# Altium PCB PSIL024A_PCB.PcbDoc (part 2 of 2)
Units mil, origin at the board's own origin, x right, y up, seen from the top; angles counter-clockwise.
Board outline 5700 x 3550 mil, 4 copper layers (Top Layer, MidLayer1, MidLayer2, Bottom Layer), stack 61.2 mil thick; 205 components, 107 nets, 481 pads, 240 vias.
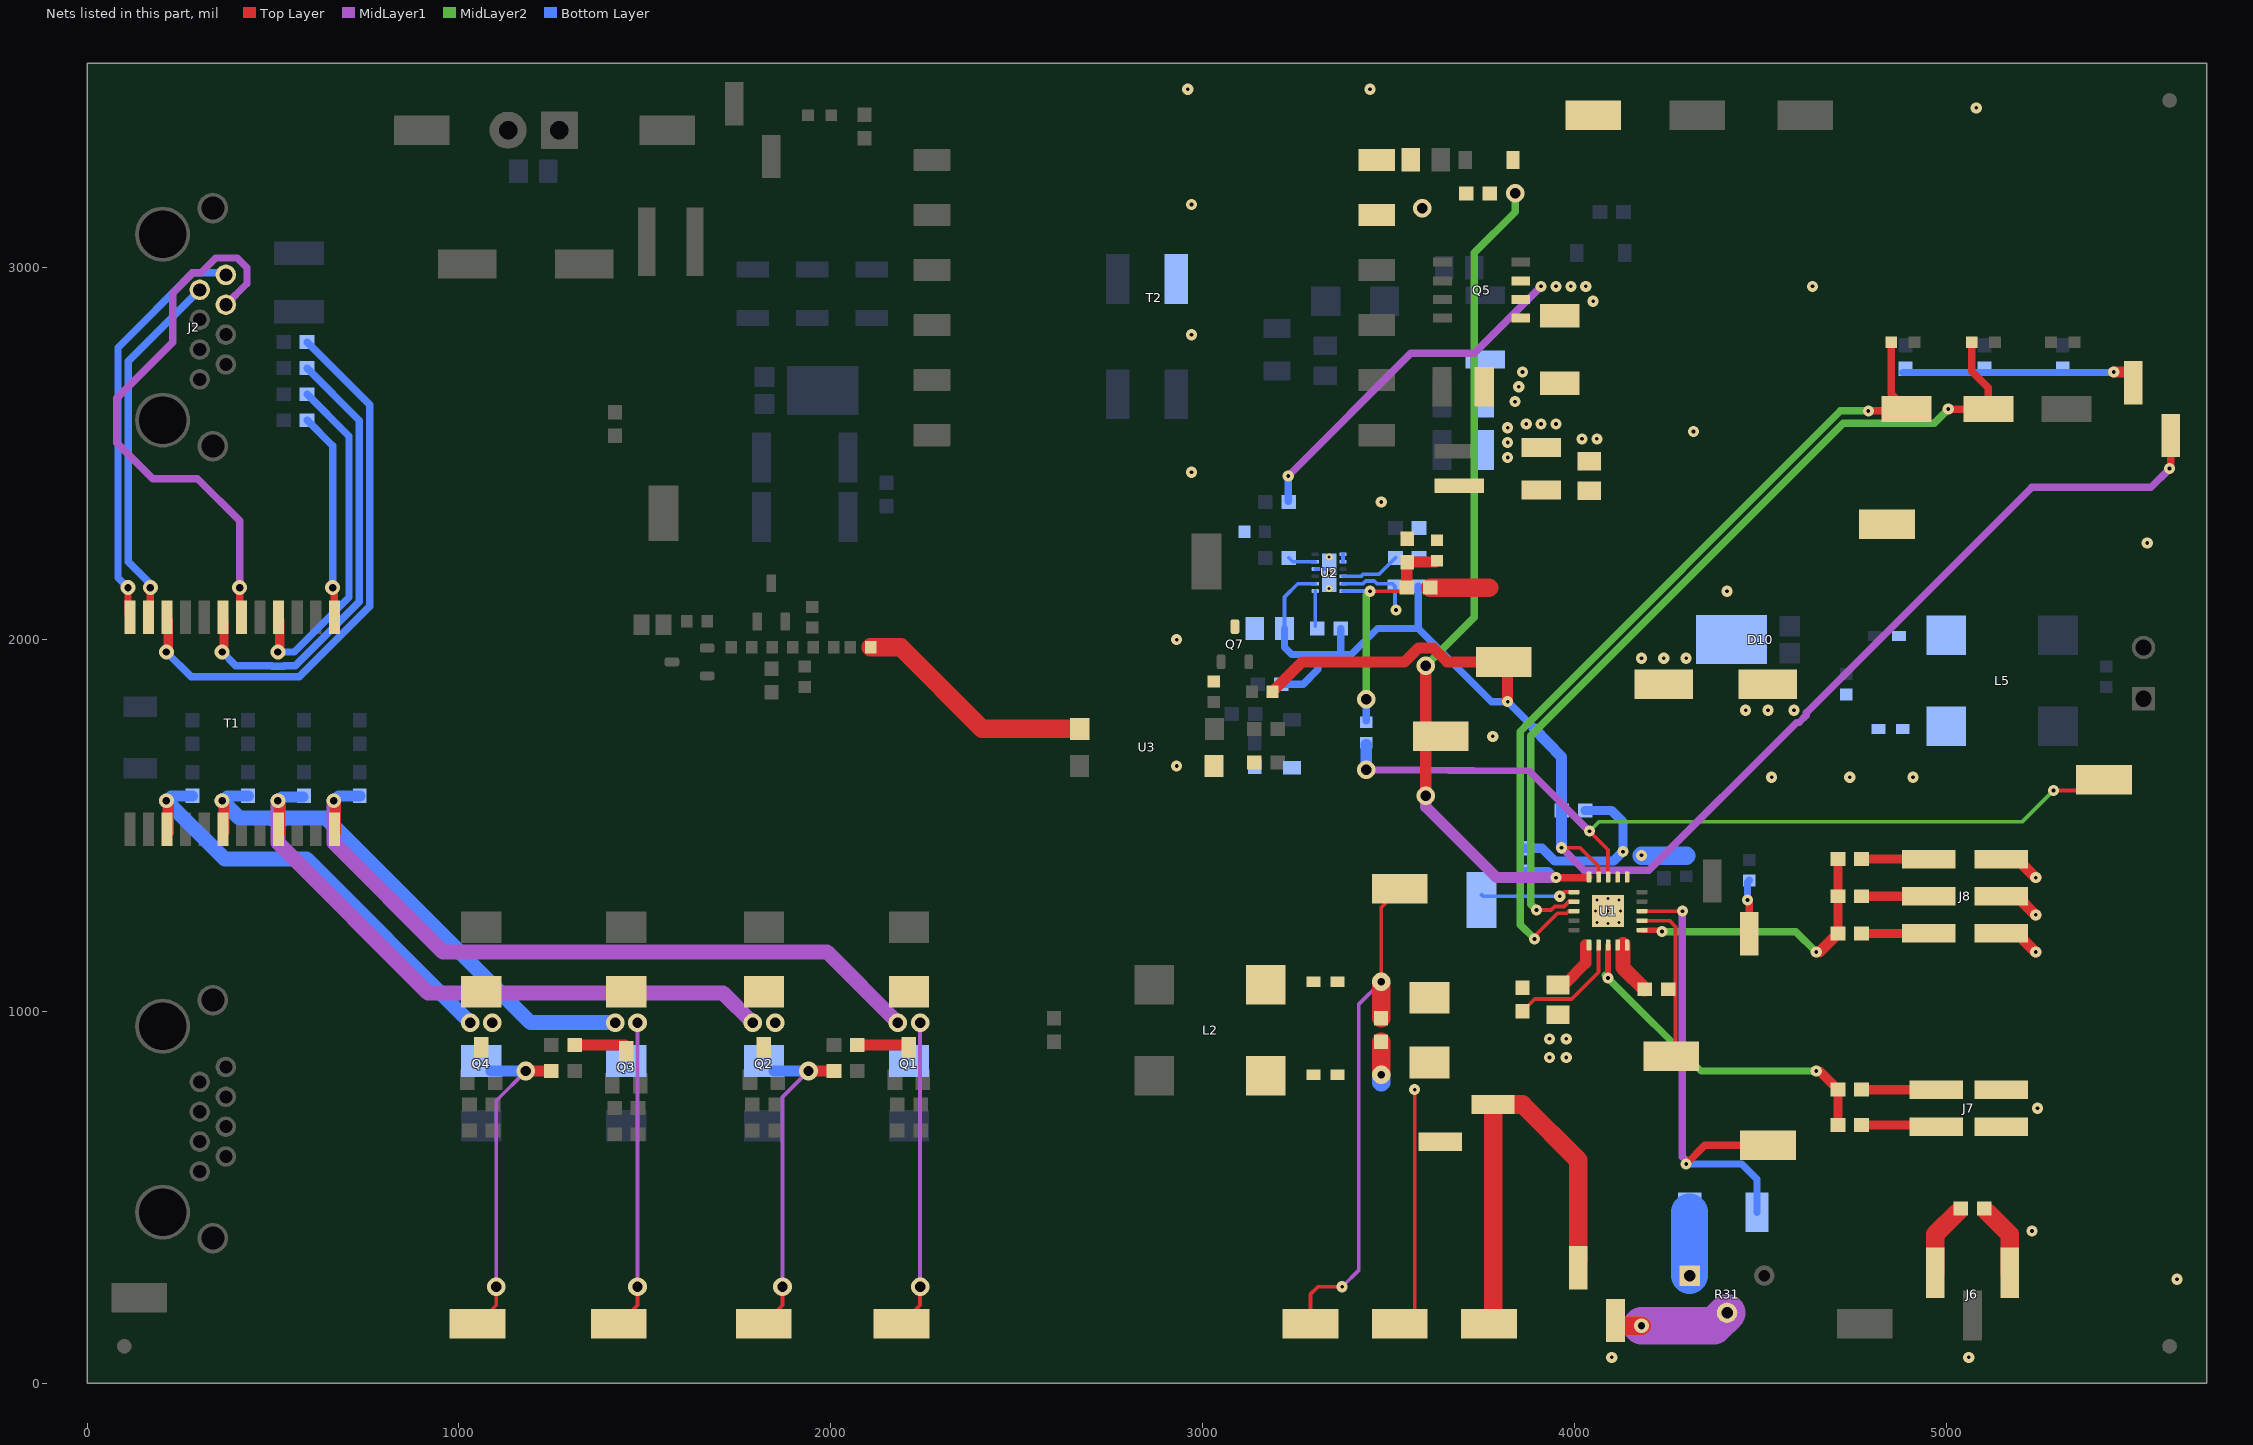
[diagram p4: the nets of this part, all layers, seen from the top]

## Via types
v1: diameter 30, hole 10, Top Layer to Bottom Layer, 128 vias
v2: diameter 50, hole 28, Top Layer to Bottom Layer, 77 vias
v3: diameter 40, hole 20, Top Layer to Bottom Layer, 21 vias
v4: diameter 19.68, hole 7.87, Top Layer to Bottom Layer, 8 vias
v5: diameter 20, hole 8, Top Layer to Bottom Layer, 4 vias
v6: diameter 50, hole 20, Top Layer to Bottom Layer, 2 vias

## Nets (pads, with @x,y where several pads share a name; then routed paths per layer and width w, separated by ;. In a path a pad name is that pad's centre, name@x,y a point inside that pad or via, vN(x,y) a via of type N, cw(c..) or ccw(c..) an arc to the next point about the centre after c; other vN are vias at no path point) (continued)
NetJ2_6: J2.6 T1.6 | length 1509.2
  Top Layer w20: T1.6@410,2065.04 v3(410,2140)
  MidLayer1 w20: J2.6@372.99,2900.63 430,2957.64 430,3000 403.62,3026.38 346.38,3026.38 306.22,2986.22 284.09,2986.22 230,2932.13 230,2799.42 80,2649.42 80,2530 176.77,2433.23 296.77,2433.23 410,2320 v3(410,2140)
NetJ2_7: J2.7 T1.11 | length 979.6
  Top Layer w20: T1.11@170,2065.04 v3(170,2140)
  Bottom Layer w20: v3(170,2140) 170,2150 111.04,2208.96 111.04,2748.91 J2.7@302.91,2940.79
NetJ2_8: J2.8 T1.12 | length 1109.7
  Top Layer w20: T1.12@110,2065.04 v3(110,2140)
  Bottom Layer w20: v3(110,2140) 83.17,2166.83 83.17,2785.29 284.09,2986.22 372.99,2986.22 J2.8@372.99,2980.94
NetJ4_1: J4.1 R17.1 | length 140.4
  Top Layer w20: J4.1@4470,1209.13 v1@4470,1295
  Bottom Layer w20: v1(4465,1300) 4465,1347.44 R17.1@4470,1352.44
NetJ5_2: J5.2 R20.2 R21.2 R22.2 | length 623.7
  Top Layer w30: v1(5450,2720) J5.2@5510,2720
  Bottom Layer w20: R20.2@4882.8,2718.49 5312.8,2718.49 v1@5446.51,2718.49
NetJ6_1: J6.1 R19.1 | length 187.8
  Top Layer w50: J6.1@4970,297.5 4970,401.5 R19.1@5030,460
NetJ7_2: J7.2 R24.1 | length 203.1
  Top Layer w25: R24.1@4771.5,695 4967.5,695 J7.2@4972.5,690
NetJ7_4: J7.4 R25.1 | length 201
  Top Layer w25: R25.1@4771.5,790 J7.4@4972.5,790
NetJ8_2: J8.2 R27.1 | length 178.5
  Top Layer w25: R27.1@4771.5,1210 J8.2@4950,1210
NetJ8_4: J8.4 R28.1 | length 181.1
  Top Layer w25: R28.1@4771.5,1310 J8.4@4952.56,1310
NetJ8_6: J8.6 R29.1 | length 178.5
  Top Layer w25: R29.1@4771.5,1410 J8.6@4950,1410
NetJ10_2: J10.2 R31.2 | length 300.4
  Top Layer w50: J10.2@4124.13,155 v3(4180,155)
  MidLayer1 w100: v3(4180,155) 4375,155 R31.2@4410,190
NetL1_1: L1.1 L2.1
NetL2_4: L2.4 L3.1
NetL4_1: L4.1 L5.1
NetL5_4: L5.4 L6.1
NetQ5_1: Q5.1 Q5.2 Q5.3 R38.2 R42.2 | length 959.8
  MidLayer1 w20: v1(3230,2440) 3560,2770 3730,2770 v1(3910,2950)
  Bottom Layer w20: R42.2@3230,2371.5 v1(3230,2440)
  other v1: 4050,2910 3950,2950 3990,2950 4030,2950
NetR5_1: R5.1 T1.10 | length 1520.1
  Top Layer w25: v3(213.15,1966.85) 218.15,1971.85 T1.10@218.15,2051.89
  Bottom Layer w20: v3(213.15,1966.85) 280,1900 570,1900 760,2090 760,2631.5 R5.1@591.5,2800
NetR6_1: R6.1 T1.7 | length 1229.6
  Top Layer w25: v3(363.15,1966.85) 368.15,1971.85 T1.7@368.15,2051.89
  Bottom Layer w20: v3(363.15,1966.85) 400,1930 496.44,1930 497.46,1928.98 528.84,1928.98 529.86,1930 560,1930 732.13,2102.13 732.13,2589.37 R6.1@591.5,2730
NetR7_1: R7.1 T1.4 | length 932.1
  Top Layer w25: v3(513.15,1966.85) 518.15,1971.85 T1.4@518.15,2051.89
  Bottom Layer w20: v3(513.15,1966.85) 557.43,1966.85 704.25,2113.67 704.25,2547.24 R7.1@591.5,2660
NetR8_1: R8.1 T1.1 | length 570.4
  Top Layer w10: v3(660,2140) v3@665,2135
  Top Layer w20: T1.1@665,2060.04 v3@665,2135
  Bottom Layer w20: R8.1@591.5,2590 660,2521.5 v3(660,2140) v3@660,2130
NetR23_1: R23.1 U1.2 | length 320.4
  Top Layer w10: R23.1@3860.25,1001 3892.62,1033.38 3992.33,1033.38 4064.41,1105.45 U1.2@4064.41,1178.46
NetR24_2: R24.2 R25.2 U1.3 | length 936.8
  Top Layer w15: v1(4090,1090) U1.3@4090,1178.46
  Top Layer w25: v1(4650,840) 4658.5,840 R25.2@4708.5,790 R24.2@4708.5,695
  MidLayer2 w20: v1@4082.5,1097.5 v1(4090,1090) 4340,840 v1(4650,840)
NetR26_1: R26.1 TP9.1 U1.13 | length 2315.6
  Top Layer w10: v1@4045,1485 v1(4040,1485) 4090,1435 U1.13@4090,1361.54 ; v1(5288,1594.5) 5395.25,1594.5 TP9.1@5423.75,1623
  MidLayer1 w20: v2(3440,1650) 3878.25,1646.75 v1(4040,1485)
  MidLayer2 w10: v1(4040,1485) 4065,1510 5203.5,1510 v1(5288,1594.5)
  Bottom Layer w30: v2@3440,1660 R26.1@3440,1718.5
NetR27_2: R27.2 R28.2 R29.2 U1.6 | length 766.6
  Top Layer w10: v1@4235,1210 v1(4235,1215) ; v1(4650,1160) v1@4658.5,1160
  Top Layer w15: U1.6@4181.54,1218.82 v1@4226.18,1218.82
  Top Layer w25: R27.2@4708.5,1210 R28.2@4708.5,1310 R29.2@4708.5,1410
  Top Layer w30: v1@4658.5,1160 R27.2@4708.5,1210
  MidLayer2 w20: v1(4235,1215) 4595,1215 v1(4650,1160)
NetR30_1: R30.1 R31.1 | length 169.4
  Bottom Layer w100: R31.1@4309.45,290.55 R30.1@4309.45,460
NetR30_2: R30.2 TP14.1 U1.8 | length 1327.2
  Top Layer w10: U1.8@4181.54,1270 v1(4290,1270)
  Top Layer w20: v1(4300,590) 4350,640 TP14.1@4520,640
  MidLayer1 w20: v1(4290,1270) 4290,610 v1@4305,595
  Bottom Layer w20: v1(4300,590) 4450,590 4490.55,549.45 R30.2@4490.55,460
NetR32_1: R32.1 TP17.1 U1.7 | length 433.2
  Top Layer w10: U1.7@4181.54,1244.41 4255,1244.41 4271.5,1227.92 4271.5,1070 TP17.1@4271.5,891.5
NetR39_2: R39.2 T2.6
NetR40_2: pad.11 R40.2 U2.11 | length 213.5
  Bottom Layer w10: U2.11@3377.4,2150.47 3431.05,2150.47 3438.45,2157.87 3461.55,2157.87 3468.95,2150.47 3510.2,2150.47 R40.2@3516.97,2143.7 3516.97,2083.03 v1(3520,2080)
NetR41_1: R41.1 U2.5 | length 75.4
  Bottom Layer w10: R41.1@3231.5,2220 3241.97,2209.53 U2.5@3302.6,2209.53
NetR43_2: pad.10 R43.2 U2.10 | length 161.7
  Bottom Layer w10: U2.10@3377.4,2170.16 3425.46,2170.16 3431.05,2175.75 3474.25,2175.75 R43.2@3518.5,2220
NetR54_1: R54.1 U3.1 | length 652.3
  Top Layer w50: R54.1@2107.56,1980 2187.56,1980 2407.56,1760 ; 2408.17,1760 U3.1@2669.39,1760
NetR63_2: R63.2 U2.1 | length 94.9
  Bottom Layer w10: R63.2@3302.6,2035.91 U2.1@3302.6,2130.79
NetTP16_1: TP16.1 U1.16 | length 255.2
  Top Layer w10: v1(3960,1310) 3971.18,1321.18 U1.16@3998.46,1321.18
  Bottom Layer w10: TP16.1@3749.74,1314.36 3754.1,1310 v1(3960,1310)
PR12: C1.1 D1.2 D6.1 Q1.3 R10.2 T1.24 TP1.1 | length 2935.1
  Top Layer w10: TP1.1@2190,160 2240,210 v2(2240,260)
  Top Layer w30: T1.24@668.15,1481.81 v3@668.15,1561.85 ; R10.2@2071.5,910 2190,910
  MidLayer1 w10: v2(2240,260) v2(2240,970)
  MidLayer1 w40: v3(663.15,1566.85) 663.15,1453.7 956.85,1160 1990,1160 v2(2180,970)
  Bottom Layer w30: v3(663.15,1566.85) 676.3,1580 C1.1@733.15,1580
PR36: C2.1 D2.2 D7.1 Q2.3 R9.2 T1.21 TP2.1 | length 2632.6
  Top Layer w10: TP2.1@1820,160 1870,210 v2(1870,260)
  Top Layer w30: T1.21@518.15,1481.81 v3@518.15,1561.85 ; v2(1940,840) R9.2@2008.5,840
  MidLayer1 w10: v2(1870,260) 1870,770 v2(1940,840)
  MidLayer1 w40: v3(513.15,1566.85) 513.15,1453.7 916.85,1050 1710,1050 v2(1790,970)
  Bottom Layer w30: v3(513.15,1566.85) 523.15,1576.85 C2.1@580,1576.85 ; D7.1@1847.01,840 v2(1940,840)
  other v2: 1850,970
PR45: C3.1 D3.2 D8.1 Q3.3 R12.2 T1.18 TP3.1 | length 2434.6
  Top Layer w10: TP3.1@1430,160 1480,210 v2(1480,260)
  Top Layer w30: T1.18@368.15,1481.81 v3@368.15,1561.85 ; R12.2@1311.5,910 Q3.3@1446.69,910
  MidLayer1 w10: v2(1480,970) 1480,280 v2@1500,260
  Bottom Layer w30: v3(363.15,1566.85) 376.3,1580 C3.1@433.15,1580
  Bottom Layer w40: v3(363.15,1566.85) 410,1520 492.3,1520 493.32,1518.98 532.98,1518.98 534,1520 642.3,1520 1192.3,970 v2(1420,970)
PR78: C4.1 D4.2 D9.1 Q4.3 R11.2 T1.15 TP4.1 | length 2114.9
  Top Layer w10: TP4.1@1050,160 1100,210 v2(1100,260)
  Top Layer w30: T1.15@218.15,1481.81 v3@218.15,1561.85 ; v2(1180,840) R11.2@1248.5,840
  MidLayer1 w10: v2(1100,260) 1100,760 v2(1180,840)
  Bottom Layer w30: v3(213.15,1566.85) 226.3,1580 C4.1@283.15,1580 ; D9.1@1087.01,840 v2(1180,840)
  Bottom Layer w40: v3(213.15,1566.85) 370,1410 590,1410 v2(1030,970)
  other v2: 1090,970
RTN: C13.2 C15.1 C16.2 C17.2 C18.2 C21.1 C22.2 C23.2 C24.2 C25.2 C33.2 C34.2 C35.2 C36.2 C38.2 C39.2 C40.2 C41.2 C43.2 D19.2 L6.2 pad.4 pad.7 pad.8 Q7.3 R18.1 R36.1 R37.1 R38.1 R43.1 T2.5 TP10.1 TP23.1 U1.11 U1.12 U2.4 U2.7 U2.8 U2.13@3340,2180 U3.3 | length 647.3
  Bottom Layer w10: U2.4@3302.6,2189.84 U2.13@3330.16,2189.84 ; U2.8@3377.4,2209.53 U2.7@3377.4,2229.21
  Bottom Layer w25: C16.2@3868.25,1439.25 3912.24,1439.25 3946.61,1404.88 4104.63,1404.88 v1@4130,1430.25 ; C18.2@4028.25,1540.5 4099.25,1540.5 4130,1509.75 v1@4130,1430.25 ; v1@4130.75,1430.25 v1@4130,1430.25
  Bottom Layer w50: v1@4181.14,1418.86 C15.1@4300,1418.86
  other v1: 4180,1420 4130,1430 4530,1630 4740,1630 4910,1630 2930,1660 3780,1740 4460,1810 4520,1810 4590,1810 2930,2000 4410,2130 5540,2260 3480,2370 2970,2450 3820,2490 3820,2530 4020,2540 4060,2540 4320,2560 3820,2570 3870,2580 3910,2580 3950,2580 3840,2640 3850,2680 3860,2720 2970,2820 4640,2950 2970,3170 5080,3430 2960,3480 3450,3480
  other v2: 3590,3160
  other v4: 3340,2137.68 3340,2180 3340,2222.32
TPH: D11.1 TP11.1 U1.18 | length 2310.9
  Top Layer w10: v1(3892.5,1195) 3892.5,1202.5 3954.25,1264.25 3978.95,1264.25 3984.7,1270 U1.18@3998.46,1270
  Top Layer w20: v1(4790,2615) 4887.82,2615 TP11.1@4892.8,2619.98 4851.3,2661.48 D11.1@4851.3,2799.98
  MidLayer2 w20: v1(3892.5,1195) 3854.25,1233.25 3854.25,1753.09 3860,1758.84 3860,1759.42 3870,1769.42 3870,1770 4715,2615 v1(4790,2615)
TPL: D12.1 TP12.1 U1.17 | length 2380
  Top Layer w10: v1(3897.75,1272.75) 3936.57,1272.75 3947.2,1283.38 3948.45,1282.13 3971.55,1282.13 3985.01,1295.59 U1.17@3998.46,1295.59
  Top Layer w20: v1(5005,2620) TP12.1@5112.8,2619.98 5112.8,2677.2 5067.86,2722.14 D12.1@5067.86,2799.98
  MidLayer2 w20: v1(3897.75,1272.75) 3882.13,1288.37 3882.13,1741.55 3890,1749.42 3890,1750 4722.13,2582.13 4967.13,2582.13 v1(5005,2620)
UVLO: C33.1 pad.12 R26.2 R34.1 R37.2 U2.12 | length 663.4
  Top Layer w10: v1(3450,2130) R34.1@3560,2130
  Top Layer w30: R34.1@3548.5,2140 R37.2@3548.5,2207.01 ; R37.2@3550,2208.5 C33.1@3626.06,2208.5
  MidLayer2 w20: v2(3440,1840) v1@3440,2120
  Bottom Layer w10: U2.12@3377.4,2130.79 v1@3449.21,2130.79
  Bottom Layer w20: R26.2@3440,1781.5 v2(3440,1840)
VCIN: C16.1 C39.1 D17.1 TP25.1 U1.15 | length 2355.7
  Top Layer w20: v1(3950,1360) 4037.28,1360 U1.15@4038.82,1361.54
  Top Layer w30: v2(3600,1580) v2(3600,1930)
  MidLayer1 w30: v2(3600,1580) 3600,1550 3790,1360 v1(3950,1360)
  MidLayer2 w20: v2(3600,1930) 3730,2060 3730,3040 3840,3150 v2(3840,3200)
  Bottom Layer w25: C16.1@3868.75,1376.5 3928.5,1376.5 3945,1360 v1(3950,1360)
VCOUT: C18.1 C40.1 J5.1 pad.2 R40.1 R45.2 R62.2 R63.1 TP26.1 U1.14 U2.2 | length 4881.1
  Top Layer w10: v1(3965,1440.25) 4014.75,1440.25 4064.41,1390.59 U1.14@4064.41,1361.54
  Top Layer w20: v1@5602.8,2462.2 J5.1@5602.8,2549.13
  Top Layer w30: R62.2@3187.56,1860 3267.56,1940 3542.3,1940 3580.17,1977.87 3619.83,1977.87 3657.7,1940 TP26.1@3810,1940 ; v1(3820,1833.26) TP26.1@3820,1940
  MidLayer1 w20: v1(3965,1440.25) 4025.25,1380 4200,1380 4597.13,1777.13 4603.62,1777.13 4622.87,1796.38 4622.87,1802.87 5230,2410 5550,2410 v1(5600,2460)
  Bottom Layer w10: C40.1@3220,2030 3220,2114.61 3255.86,2150.47 U2.2@3302.6,2150.47
  Bottom Layer w20: R45.2@3211.5,1880 3270,1880 3310,1920 3310,1960 ; C40.1@3220,2030 3220,1980 3240,1960 3310,1960 ; 3371.5,1961.5 R63.1@3371.5,2030 ; R40.1@3579.96,2143.7 3579.96,2030.04 ; v1(3820,1833.26) 3776.74,1833.26 3579.96,2030.04 ; v1(3820,1833.26) 3891.65,1761.65 ; 3310,1960 3400,1960 3470.04,2030.04 3579.96,2030.04
  Bottom Layer w30: 3890.83,1760.84 3965.25,1684.75 3965.1,1540.5 v1(3965,1440.25)
VDD: C8.1 C17.1 C19.1 C21.2 C22.1 D5.1 D10.3 L1.2 L7.1 R23.2 R34.2 TP7.1 TP8.1 U1.1 | length 1721.3
  Top Layer w10: TP7.1@3290,160 3290,240 3310,260 v1(3375,260) ; v6@3480,1072.44 v6(3480,1080) 3480,1280 TP8.1@3530,1330 ; C19.1@3955.5,1071.25 C19.1@3981.25,1071.25
  Top Layer w30: C19.1@3972.43,1072.43 4030,1130 4030,1179.65
  Top Layer w50: C8.1@3480,981.5 v6@3480,1072.44 ; R34.2@3611.5,2140 3770,2140
  MidLayer1 w10: v1(3375,260) 3420,305 3420,1020 v6(3480,1080)
  other v1: 4180,1950 4240,1950 4300,1950
VSS: C19.2 J6.3 J7.1 J7.3 J8.1 J8.3 J8.5 J9.1 J10.1 R19.2 R32.2 TP18.1 U1.4 U1.5 U1.21@4090,1270 | length 1697.8
  Top Layer w10: J10.1@4000,320.87 J10.1@4010,330.87
  Top Layer w30: J8.1@5190,1210 v1(5240,1160) ; J8.3@5190,1310 v1(5240,1260) ; J8.5@5190,1410 v1(5240,1360)
  Top Layer w40: 4130,1180 4130,1118.5 R32.2@4188.5,1060
  Top Layer w50: TP18.1@3780.87,170.87 J9.1@3780.87,750 3860,750 4010,600 J10.1@4010,330.87 ; R19.2@5110,460 5170,401.5 J6.3@5170,297.5
  other v1: 4100,70 5060,70 5620,280 5230,410 5245,740 3932.5,876.5 3977.5,876.5 3932.5,926.5 3977.5,926.5
  other v4: 4090,1236.54 4056.54,1270 4090,1270 4123.46,1270 4090,1303.46
  other v5: 4060,1240 4120,1240 4060,1300 4120,1300
VSS1: C8.2 D5.2 J9.2 L3.2 TP15.1 | length 755.1
  Top Layer w10: TP15.1@3530,160 3570,200 v1(3570,790)
  Top Layer w50: v6(3480,830) C8.2@3480,918.5
  Bottom Layer w50: v6@3480,810 v6(3480,830)
pads on no net: FID1.1 FID2.1 FID3.1 FID4.1 FID5.1 FID6.1 H1.0 H2.0 H3.0 H4.0 R31.3 SH-J1.0 SH-J2.0 SH-J3.0 SH-J4.0 SH-J5.0 SH-J6.0 SH-J7.0 SH-J8.0 T2.7 T2.10 U1.20 U1.21@4066.77,1246.77 U1.21@4066.77,1293.23 U1.21@4113.23,1246.77 U1.21@4113.23,1293.23 U2.13@3340,2153.03 U2.13@3340,2206.97
copper on no net:
  other v1: 2380,840

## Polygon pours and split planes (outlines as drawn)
VDD on Top Layer "TOP_LAYER_VDD_P106" (solid, remove dead copper, pour order 106): 3620,2430 3620,2340 3770,2340 3770,2430
GND on Top Layer "TOP_LAYER_GND_P088" (solid, remove dead copper, pour order 88): 2800,1580 890,1580 890,3090 890,3510 2800,3510
EARTH on Top Layer "TOP_LAYER_EARTH_P028" (solid, remove dead copper, pour order 28): 40,1480 2550,1480 2550,40 40,40
EARTH on Top Layer "TOP_LAYER_EARTH_P020" (solid, remove dead copper, pour order 20): 793.74,3240 786.81,70 40,70 40,3240
VSS on Top Layer "TOP_LAYER_VSS_P014" (solid, remove dead copper, pour order 14): 4050,1310 4130,1310 4510,1310 4605,1310 4765,1470 5660,1470 5660,40 4050,40
RTN on Top Layer "TOP_LAYER_RTN_P010" (solid, remove dead copper, pour order 10): 4110,1345 4146.91,1345 4421.91,1580 4730,1580 4735,2990 4420,2990 4420,1890 4420,1845 4110,1581.04
VDD on Top Layer "TOP_LAYER_VDD_P008" (solid, remove dead copper, pour order 8): 3340,1045 3698.58,1045 3698.58,1048.58 3910,1048.58 3890,1330 3890,1410 4322.25,1705.09 4318.74,2430 3955,2430 3955,1790 3690,1540 3548.57,1405.71 3340,1405.71
VSS on Top Layer "TOP_LAYER_VSS_P006" (solid, remove dead copper, pour order 6): 3740,1020 3740,725 4150,725 4150,1000 4150,1200 4135,1200 4125,1200 4120,1200 4115,1200 4115,1105 4030,1020 4025,1025 3740,1025
VSS1 on Top Layer "TOP_LAYER_VSS1_P004" (solid, remove dead copper, pour order 4): 3450,620 3685,620 3685,1010 3690,1015 3450,1015
NetC7_1 on Top Layer "TOP_LAYER_NETC7_1_P002" (solid, remove dead copper, pour order 2): 2630,960 2520,960 2520,1110 2630,1110
NetC7_2 on Top Layer "TOP_LAYER_NETC7_2_P000" (solid, remove dead copper, pour order 0): 2640,785 2525,785 2525,940 2640,940
RTN on Top Layer "TOP_LAYER_RTN_P064" (solid, remove dead copper, pour order 64): 3345,1870 3345,1578.98 3590,1578.98 3590,1860 3585,1865 3580,1870
RTN on Top Layer "TOP_LAYER_RTN_P080" (solid, remove dead copper, pour order 80): 5637.68,2230 4867.68,2230 4867.68,3510 5637.68,3510
VDD on Top Layer "TOP_LAYER_VDD_P114" (solid, remove dead copper, pour order 114): 3640.35,2430 3640.35,2110 3970.35,2110 3970.35,2430 3640.35,2430
RTN on Top Layer "TOP_LAYER_RTN_P116" (solid, remove dead copper, pour order 116): 5670,1580 2900,1580 2900,3510 5670,3510
EARTH on Bottom Layer "BOTTOM_LAYER_EARTH_P034" (solid, remove dead copper, pour order 34): 40,3240 790,3240 790,1480 40,1480
EARTH on Bottom Layer "BOTTOM_LAYER_EARTH_P026" (solid, remove dead copper, pour order 26): 2550,1480 2550,40 40,40 40,1480
VSS on Bottom Layer "BOTTOM_LAYER_VSS_P012" (solid, remove dead copper, pour order 12): 4050,1310 4130,1310 4510,1310 4605,1310 4765,1470 5660,1470 5660,40 5530,40 4050,40
RTN on Bottom Layer "BOTTOM_LAYER_RTN_P054" (solid, remove dead copper, pour order 54): 5120,1584.51 2900,1584.51 2900,3510 5120,3510
GND on Bottom Layer "BOTTOM_LAYER_GND_P062" (solid, remove dead copper, pour order 62): 2800,1580 890,1580 890,3510 2800,3510
RTN on Bottom Layer "BOTTOM_LAYER_RTN_P070" (solid, remove dead copper, pour order 70): 3335.16,1874.84 3335.16,1583.82 3580.16,1583.82 3580.16,1864.84 3575.16,1869.84 3570.16,1874.84
VSS on Bottom Layer "BOTTOM_LAYER_VSS_P072" (solid, remove dead copper, pour order 72): 3740,1020 3740,720 4155,720 4155,1305 4050.44,1305 4050,1304.56 4056.22,1298.34 4056.22,1155.35 4056.22,1076.07 4050,1069.85 4010,1029.85 4010,1025 3740,1025
RTN on Bottom Layer "BOTTOM_LAYER_RTN_P082" (solid, remove dead copper, pour order 82): 5670,2190 4880,2190 4880,3510 5670,3510
GND on MidLayer1 "MIDLAYER1_GND_P094" (solid, remove dead copper, pour order 94): 2800,1580 890,1580 890,3090 890,3510 2800,3510
EARTH on MidLayer1 "MIDLAYER1_EARTH_P030" (solid, remove dead copper, pour order 30): 75.36,1475 2550,1475 2550,40 70.36,40 70.36,1470
EARTH on MidLayer1 "MIDLAYER1_EARTH_P022" (solid, remove dead copper, pour order 22): 790,3240 790,40 40,40 40,3240
VSS on MidLayer1 "MIDLAYER1_VSS_P016" (solid, remove dead copper, pour order 16): 4050,1300 4130,1300 4510,1300 4605,1300 4765,1460 5660,1460 5660,40 5550,40 4050,40
RTN on MidLayer1 "MIDLAYER1_RTN_P066" (solid, remove dead copper, pour order 66): 3340,1875.66 3340,1622.75 3585,1622.75 3585,1865.66 3580,1870.66 3575,1875.66
no net on MidLayer1 "MIDLAYER1_NONET_P074" (solid, remove dead copper, pour order 74): 4117,1472 4115,1470 4115,1345 4145,1345 4380,1580 4735,1580 4735,2990 4420,2990 4420,1775
RTN on MidLayer1 "MIDLAYER1_RTN_P050" (solid, remove dead copper, pour order 50): 5670,1580 2900,1580 2900,3510 5670,3510
RTN on MidLayer1 "MIDLAYER1_RTN_P078" (solid, remove dead copper, pour order 78): 5630,2230 4860,2230 4860,3475 5630,3475
RTN on MidLayer2 "MIDLAYER2_RTN_P076" (solid, remove dead copper, pour order 76): 5670,2220 4900,2220 4900,3510 5670,3510
EARTH on MidLayer2 "MIDLAYER2_EARTH_P024" (solid, remove dead copper, pour order 24): 789.44,3240 789.44,39.98 590,39.98 39.98,39.98 44.06,3240
EARTH on MidLayer2 "MIDLAYER2_EARTH_P032" (solid, remove dead copper, pour order 32): 41.82,1480 2550,1480 2550,40 39.96,40
VSS on MidLayer2 "MIDLAYER2_VSS_P018" (solid, remove dead copper, pour order 18): 4050,1310 4130,1310 4510,1310 4605,1310 4765,1470 5660,1470 5660,40 4050,40
RTN on MidLayer2 "MIDLAYER2_RTN_P052" (solid, remove dead copper, pour order 52): 5150,1580 2900,1580 2900,3510 5150,3510
GND on MidLayer2 "MIDLAYER2_GND_P060" (solid, remove dead copper, pour order 60): 2803.54,1581.18 893.31,1581.18 893.31,3091.19 893.31,3511.19 2800,3510
RTN on MidLayer2 "MIDLAYER2_RTN_P068" (solid, remove dead copper, pour order 68): 3340,1875 3340,1583.98 3585,1583.98 3585,1865 3580,1870 3575,1875
EARTH on MidLayer2 "MIDLAYER2_EARTH_P104" (solid, pour order 104): 750,2350 750,1500 544.04,1500 544.04,2350

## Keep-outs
Keep-Out Layer:
  text ".Layer_Name" at 577,-858.49 h60

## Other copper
Top Layer:
  rectangle net NetC37_1: 1910,2530 2350,2720
  rectangle net NetD15_2: 3830,3000 3950,3130
  rectangle net NetC20_2: 3570,2480 3760,2600
  rectangle net NetC32_1: 3430,2790 3800,3040
  rectangle net NetC20_2: 3440,2480 3670,2730
  rectangle net NetC44_2: 1770,1910 1860,2000
  rectangle net NetD21_2: 1650,1960 1750,2070
  rectangle net NetC44_1: 1880,1910 1970,2060
  rectangle net NetD21_2: 1990,1960 2070,2070
  rectangle net RTN: 4115,1345 4145,1475
  rectangle net NetC14_2: 5250,1710 5660,1890
  rectangle net NetC14_1: 5250,1910 5660,2095
  rectangle net NetC46_1: 1530,1930 1630,2070
  rectangle net VSS: 3910,860 4000,1020
  rectangle net NetC7_2: 1830,660 1880,840
  rectangle net NetC10_1: 1760,660 1810,840
  rectangle net NetC7_2: 2220,660 2270,840
  rectangle net NetC11_1: 1390,650 1440,840
  rectangle net NetC7_2: 1070,660 1120,840
  rectangle net NetC12_1: 1000,660 1050,840
  rectangle net PR12: 2160,880 2260,1090
  rectangle net PR45: 1400,880 1500,1090
  rectangle net PR78: 1010,880 1110,1090
  rectangle net PR36: 1770,880 1870,1090
  rectangle net VSS: 5080,660 5260,820
  rectangle net NetC7_2: 1460,650 1510,840
  rectangle net NetC9_1: 2149.29,660 2200,840
  rectangle net VDD: 3460,1050 3990,1110
  rectangle net NetC37_1: 2100,2680 2320,2730
  rectangle net NetC37_1: 2100,2680 2200,2790
  rectangle net NetC28_1: 1610,2960 2330,3180
  rectangle net NetC27_1: 1220,2970 1530,3420
  rectangle net NetL2_4: 3120,770 3320,880
  rectangle net NetL1_1: 3120,1020 3320,1130
  rectangle net VDD: 3340,1020 3500,1110
  rectangle net VSS1: 3340,620 3490,880
  rectangle net NetQ5_1: 3830,2840 4080,2980
  rectangle net NetR39_2: 3420,3260 3580,3320
  rectangle net NetD17_2: 3620,3260 3720,3320
  rectangle net VCIN: 3810,3180 3860,3320
  rectangle net VCIN: 3750,3180 3860,3220
  pour cut-out: 5670,2190 4950,2190 4950,1520 5670,1520
  region net VSS: 4150,1160 4110,1160 4110,1250 4140,1250 4140,1200 4150,1190
  text ".Layer_Name" at 577,-858.49 h60
MidLayer1:
  rectangle net NetC14_2: 5250,1710 5660,1890
  rectangle net NetC14_1: 5250,1910 5660,2095
  rectangle net NetC28_1: 1610,2960 2330,3180
  rectangle net NetC27_1: 1220,2970 1530,3420
  pour cut-out: 5680,2190 4950,2190 4950,1550 5680,1550
MidLayer2:
  rectangle net NetC14_2: 5250,1715 5660,1890
  rectangle net NetC14_1: 5250,1910 5660,2095
  rectangle net NetC28_1: 1610,2960 2330,3180
  rectangle net NetC27_1: 1220,2970 1530,3420
  pour cut-out: 5670,2190 4950,2190 4950,1560 5670,1560
Bottom Layer:
  rectangle net NetC6_1: 500,2850 640,2910
  rectangle net RTN: 3710,2600 3880,2780
  rectangle net NetC32_2: 3710,2900 3810,3030
  rectangle net NetQ5_1: 3880,2840 4080,2980
  rectangle net NetC20_2: 3560,2480 3670,2740
  rectangle net NetC32_1: 3450,2810 3600,3030
  rectangle net NetC26_1: 3170,2810 3370,2870
  rectangle net NetC26_1: 3290,2760 3370,2950
  rectangle net VDD: 3450,990 3660,1120
  rectangle net VSS1: 3450,620 3690,940
  rectangle net NetC32_1: 3550,2970 3690,3030
  rectangle net NetC20_2: 2910,2580 3670,2740
  rectangle net NetD15_2: 3890,3000 4030,3140
  rectangle net NetR30_2: 4415,375 4625,535
  rectangle net NetR30_1: 4170,375 4375,535
  rectangle net NetC14_2: 5250,1710 5660,1890
  rectangle net NetC14_1: 5250,1915 5660,2095
  rectangle net PR36: 1770,830 1870,990
  rectangle net PR12: 2160,830 2260,990
  rectangle net PR78: 1010,830 1110,990
  rectangle net PR45: 1400,830 1500,990
  rectangle net NetC6_1: 500,2570 550,2910
  rectangle net NetC37_1: 1880,2590 2210,2760
  rectangle net NetC37_1: 2100,2400 2210,2590
  rectangle net NetC37_2: 2020,2260 2210,2380
  rectangle net NetC37_2: 2020,2260 2070,2560
  rectangle net NetC28_1: 1610,2960 2330,3180
  rectangle net NetC27_1: 1220,2970 1530,3420
  rectangle net NetC13_1: 4560,1930 4830,2070
  rectangle net NetL4_1: 4855.49,1960 5050,2070
  rectangle net NetL5_4: 4860,1710 5050,1820
  rectangle net NetC13_1: 4720,1890 4810,1950
  rectangle net VDD: 4160,1930 4520,2060
  pour cut-out: 5680,2200 4960,2200 4960,1550 5680,1550
  text ".Layer_Name" at 577,-858.49 h60

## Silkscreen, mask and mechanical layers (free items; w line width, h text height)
Top Overlay:
  text "LED" at 1930,3460 h40
  text "PGND" at 3980,3290 h40
  text "GATE" at 4270,3290 h40
  text "VDS" at 4570,3290 h40
  text "GND" at 850,3250 h40
  text "VOUT" at 1490,3250 h40
  text "PSIL024 REV A" at 4912,2992 h50
  text "DATA" at 670,2950 h40 r270
  text "VCOUT" at 5620,2695 h40 r90
  text "TPH" at 4830,2500 h40
  text "TPL" at 5050,2500 h40
  text "BT" at 5290,2500 h40
  text "BIAS" at 5530,2390 h40 r90
  text "LOOP" at 1310,2300 h40
  text "RTN" at 4960,2290 h40
  text "ADAPTER" at 5390,2150 h40
  text "+" at 5600,2090 h40
  text "VCOUT" at 3740,2020 h30
  text "-" at 5630,1700 h40 r90
  text "PG" at 5540,1630 h40
  text "VCIN" at 3570,1620 h40
  text "CLSB(4-PAIR)" at 5265,1490 h35
  text "Class 4" at 5315,1395 h40
  text "Class 0" at 5315,1295 h40
  text "VDD" at 3480,1210 h40
  text "APD" at 4360,1200 h30 r270
  text "Class 1" at 5315,1195 h40
  text "APD_Connect" at 4460,1130 h25 r270
  text "*" at 5140,1120 h20
  text "POE + DATA" at 680,900 h40 r270
  text "CLSA" at 5355,845 h35
  text "Class 3" at 5295,765 h40
  text "AMPS_CTL" at 4400,720 h30
  text "REF" at 4210,700 h40
  text "Class 4" at 5295,665 h40
  text "*" at 5180,610 h20
  text "PORT_CURRENT" at 3530,530 h40
  text "AMPS_Connect" at 3850,400 h30
  text "*" at 4890,380 h20
  text "MPS_DUTY" at 4960,380 h30
  text "MPS_DUTY" at 4670,310 h30
  text "PAIR78" at 940,300 h40
  text "PAIR45" at 1320,300 h40
  text "PAIR36" at 1710,300 h40
  text "PAIR12" at 2080,300 h40
  text "VSS1" at 3470,300 h40
  text "VSS" at 3710,300 h40
  text "VDD" at 3230,290 h40
  text "EARTH" at 250,180 h40
  text "R25" at 4930,130 h30
  text "VSS" at 5140,130 h30
  text ".Layer_Name" at 577,-858.49 h60
Bottom Overlay:
  text "VCOUT" at 3920,1920 h40
  text "UVLO_SEL" at 3850,1140 h40
  text ".Layer_Name" at 577,-858.49 h60
Top Paste:
  text ".Layer_Name" at 577,-858.49 h60
Bottom Paste:
  text ".Layer_Name" at 577,-858.49 h60
Top Solder:
  text ".Layer_Name" at 577,-858.49 h60
  text ".Layer_Name" at 577,-858.49 h60
Bottom Solder:
  text ".Layer_Name" at 577,-858.49 h60
Drill Guide:
  text ".Layer_Name" at 577,-858.49 h60
M1 Board Outline:
  the board outline again, w10
  text ".Layer_Name" at 577,-858.49 h60
M2 Board Dimensions:
  rectangle: 125,-400 500,-275
  rectangle: 0,-275 125,-150
  lines w7: 0,-275 1000,-275 ; 125,-400 125,-150 ; 250,-400 250,-150 ; 500,-400 500,-150 ; 750,-400 750,-150 ; 0,-400 0,-150 1000,-150 1000,-400 0,-400
  text ".Layer_Name" at 577,-858.49 h60
M3 3D STEP Top:
  text ".Layer_Name" at 577,-858.49 h60
M4 3D STEP Bottom:
  text ".Layer_Name" at 577,-858.49 h60
M5 Assembly Top:
  lines w10: -292,-930.17 6308,-930.17 ; -292,-726.83 6310,-726.83 ; -292,-523.5 -292,-1133.5 3713,-1133.5 6310,-1133.5 6310,-523.5 -291.5,-523.5 -291.5,-1133.5 1284,-1133.5 ; 2173,-1133.5 2173,-523.5 ; 3440,-726.83 3440,-523.5 ; 4280,-726.83 4280,-523.5 ; 4902,-1140 4902,-937.17
  text "COMPONENTS MARKED 'DNP' SHOULD NOT BE POPULATED." at 1153.5,-318.5 h60
  text "ASSEMBLY VARIANT:" at 1153,-434 h60
  text ".VariantName" at 2189,-434 h60
  text "PCB VIEWED FROM TOP SIDE" at -228.5,-655.67 h60
  text "BOARD #:" at 2248,-655.67 h60
  text ".PRJ_Number" at 2793.5,-655.67 h60
  text "REV:" at 3638,-655.67 h60
  text ".PCB_Rev" at 3929.5,-655.67 h60
  text "SVN REV:" at 4476,-655.67 h60
  text ".VersionControl_RevNumber" at 4982,-655.67 h60
  text "TID #:" at 2248,-859 h60
  text ".TID" at 2793.5,-859 h60
  text "PLOT NAME =" at -228.5,-1064.34 h60
  text ".plot_File_Name" at 577,-1064.34 h60
  text "GENERATED    :" at 2250,-1064.34 h60
  text ".Print_Date" at 3119.5,-1064.34 h60
  text ".Print_Time" at 3848.5,-1064.34 h60
  text "TEXAS INSTRUMENTS" at 5113,-1064.34 h60
M6 Assembly Bottom:
  circle w3.94: c3316.38,2135.71 r7.87
  lines w3.94: 3298.66,2118.98 3381.34,2118.98 3381.34,2241.02 3298.66,2241.02 3298.66,2118.98
  lines w10: -292.5,-727.33 6309.5,-727.33 ; -290.5,-930.67 6309.5,-930.67 ; 1115.5,-1140.5 1115.5,-937.67 ; 1737.5,-727.33 1737.5,-524 ; 2577.5,-727.33 2577.5,-524 ; 3844.5,-1134 3844.5,-524 ; 4733.5,-1134 6309,-1134 6309,-524 -292.5,-524 -292.5,-1134 2304.5,-1134 6309.5,-1134 6309.5,-524
  text ".Designator" at 3305,2210 h18 r180
  text "COMPONENTS MARKED 'DNP' SHOULD NOT BE POPULATED." at 6102,-318 h60
  text ".VariantName" at 5058,-434 h60
  text "ASSEMBLY VARIANT:" at 6097,-434 h60
  text ".VersionControl_RevNumber" at 1035.5,-656.17 h60
  text "SVN REV:" at 1541.5,-656.17 h60
  text ".PCB_Rev" at 2088,-656.17 h60
  text "REV:" at 2379.5,-656.17 h60
  text ".PRJ_Number" at 3224,-656.17 h60
  text "BOARD #:" at 3769.5,-656.17 h60
  text "PCB VIEWED FROM BOTTOM SIDE" at 6246,-656.17 h60
  text ".TID" at 3224,-859.5 h60
  text "TID #:" at 3769.5,-859.5 h60
  text "TEXAS INSTRUMENTS" at 904.5,-1064.84 h60
  text ".Print_Time" at 2169,-1064.84 h60
  text ".Print_Date" at 2898,-1064.84 h60
  text "GENERATED    :" at 3767.5,-1064.84 h60
  text ".plot_File_Name" at 5440.5,-1064.84 h60
  text "PLOT NAME =" at 6246,-1064.84 h60
M9 Title Sheet:
  drawing of 57 lines, arcs and shapes, not listed
  text "1" at 739.84,8036.5 h70
  text "2" at 3235.5,8036.5 h70
  text "3" at 5724.84,8036.5 h70
  text "4" at 8231.51,8036.5 h70
  text "5" at 10730.5,8036.5 h70
  text "6" at 13235.5,8036.5 h70
  text "A" at -416.5,6893.5 h70
  text "A" at 14383.5,6893.5 h70
  text "B" at -416.5,4513.5 h70
  text "B" at 14383.5,4513.5 h70
  text "C" at -416.5,2138.5 h70
  text "C" at 14383.5,2138.5 h70
  text "PROJECT TITLE:" at 11343.5,277.5 h45
  text ".PRJ_Title" at 11393.5,144.17 h70
  text "DESIGNED FOR:" at 11343.5,-23.5 h45
  text ".PRJ_Customer" at 11393.5,-163.5 h70
  text "D" at -416.5,-231.5 h70
  text "D" at 14383.5,-231.5 h70
  text "FILE NAME:" at 11343.5,-323.5 h45
  text ".PCB_File_Name_No_Path" at 11393.5,-443.5 h70
  text "Texas Instruments (TI) and/or its licensors do not warrant the accuracy or completeness of this specification" at 6374,-605.34 h45
  text "ENGINEER:" at 11343.5,-613.5 h45
  text "LAYOUT BY:" at 12848.5,-613.5 h45
  text "or any information contained therein. TI and/or its licensors do not warrant that this design will meet" at 6329.01,-718 h45
  text ".PRJ_Engineer" at 11393.5,-768.49 h70
  text ".PCB_Layout" at 12899,-768.49 h70
  text "the specifications, will be suitable for your application or fit for any particular purpose, or will operate in" at 6329.01,-830.67 h45
  text ".Layer_Name" at 577,-858.49 h60
  text "ALTIUM DESIGNER VERSION:" at 12848.5,-923.5 h45
  text "an implementation. TI and/or its licensors do not warrant that the design is production worthy. You should" at 6329.01,-943.33 h45
  text "completely validate and test your design implementation to confirm the system functionality for your application." at 6374,-1056 h45
  text ".print_Scale" at 11393.5,-1056.83 h70
  text ".Application_BuildNumber" at 12899,-1056.83 h70
  text "1" at 739.84,-1263.5 h70
  text "2" at 3235.5,-1263.5 h70
  text "3" at 5724.84,-1263.5 h70
  text "4" at 8231.51,-1263.5 h70
  text "5" at 10730.5,-1263.5 h70
  text "6" at 13235.5,-1263.5 h70
M10 Fab Notes:
  drawing of 173 lines, arcs and shapes, not listed
  text "DESIGN INFORMATION" at 12378.02,6201 h60
  text "MIN. TRACK WIDTH:" at 11733.46,6021 h60
  text "8" at 12829.7,6021 h60
  text "MIL" at 12984.46,6021 h60
  text "MIN. CLEARANCE:" at 11733.46,5889 h60
  text "0.2" at 12769.7,5889 h60
  text "mm" at 12984.46,5889 h60
  text "MIN. VIA PAD SIZE:" at 11733.46,5757 h60
  text "24" at 12799.71,5757 h60
  text "MIL" at 12984.46,5757 h60
  text "0.05mm (2MIL)" at 12428.46,5615.29 h60
  text "MINIMUM ANNULAR RING" at 11404.23,5611 h60
  text "EXTERNAL" at 13136.46,5611 h60
  text "PER" at 11604.23,5493 h60
  text "IPC-D-275 CLASS 2 LEVEL C" at 11824.23,5493 h60
  text "MIL, HOLES" at 13312.46,5380.71 h60
  text "+/-" at 12920,5380 h60
  text "+/-" at 13774,5380 h60
  text "REGISTRATION TOLERANCES:" at 11404.23,5375 h60
  text "METAL" at 12604,5375 h60
  text "5" at 13180.2,5375 h60
  text "3" at 14013.2,5375 h60
  text "MIL" at 14129.46,5375 h60
  text "+/-" at 13774,5262 h60
  text "HOLE SIZE TOLERANCE (UNLESS OTHERWISE SPECIFIED):" at 11404.23,5257 h60
  text "3" at 14013.2,5257 h60
  text "MIL" at 14129.46,5257 h60
  text "MATERIAL:" at 11329.46,5047.54 h60
  text "FR-4 High Tg" at 12315.9,4907.21 h60
  text "X" at 12170,4900 h60
  text "FR-408" at 11750.46,4898.64 h60
  text "OTHER" at 13238.46,4898.64 h60
  text "62 MIL (1.6mm) +/-10%" at 12070.56,4735.92 h60
  text "THICKNESS:" at 11404.23,4731.64 h60
  text "X" at 11942.4,4731.64 h60
  text "OTHER" at 13355.46,4731.64 h60
  text "TOLERANCE:" at 11404.23,4573.64 h60
  text "X" at 12243.53,4573.64 h60
  text "ANSI IPC-6012 TYPE 3 CLASS 2" at 12430.48,4573.64 h60
  text "OTHER +/-" at 12430.46,4417.64 h60
  text "BOW & TWIST:" at 11404.23,4260.64 h60
  text "X" at 12243.53,4260.64 h60
  text "ANSI IPC-6012 TYPE 3 CLASS 2" at 12430.48,4260.64 h60
  text "OTHER +/-" at 12430.46,4102.13 h60
  text "DRILLING:" at 11329.46,3963.64 h60
  text "REFERENCE:" at 11404.23,3846.64 h60
  text "X" at 12052.46,3846.64 h60
  text "AS SHOWN" at 12239.46,3846.64 h60
  text "X" at 12953.46,3846.64 h60
  text "NC_DRILL FILES" at 13090.46,3846.64 h60
  text "PTH MIN COPPER THICKNESS:" at 11404.23,3688.64 h60
  text "X" at 12754.46,3688.64 h60
  text "1MIL" at 12891.46,3688.64 h60
  text "OTHER" at 13388.46,3688.64 h60
  text "BOARD FINISH:" at 11329.46,3529.64 h60
  text "SILKSCREEN:" at 11484.68,3411.64 h60
  text "X" at 12433.46,3411.64 h60
  text "TOP" at 12559.46,3411.64 h60
  text "X" at 12943.46,3411.64 h60
  text "BOTTOM" at 13070.46,3411.64 h60
  text "SILKSCREEN COLOR:" at 11484.68,3244.64 h60
  text "X" at 12432.42,3244.64 h60
  text "WHITE" at 12559.46,3244.64 h60
  text "OTHER" at 13070.46,3244.64 h60
  text "X" at 12563.42,3085.44 h60
  text "GREEN" at 12690.46,3085.44 h60
  text "OTHER" at 13308.46,3085.44 h60
  text "SOLDER RESIST COLOR:" at 11484.68,3074.64 h60
  text "MATTE" at 12690.46,2915.44 h60
  text "X" at 13160,2915 h60
  text "SEMI-GLOSS" at 13308,2914.8 h60
  text "IMMERSION GOLD (ENIG)" at 12390.46,2726.92 h60
  text "ENEPIG" at 13728,2723.64 h60
  text "SURFACE FINISH:" at 11329.46,2722.64 h60
  text "X" at 12210,2720 h60
  text "IMM. TIN/SILVER OR EQUIV" at 11659,2565.64 h60
  text "OTHER" at 13090.46,2565.64 h60
  text "ARRAY/PANEL:" at 11329.46,2386.64 h60
  text "CUT AND TRIM PER M1 BOARD OUTLINE" at 12390.46,2382.35 h60
  text "N.C. ROUTE" at 12390.46,2230.64 h60
  text "V. SCORE" at 13256.46,2230.64 h60
  text "CERTIFICATION:" at 11329.46,2093.64 h60
  text "MATERIALS AND WORKMANSHIP FOR ALL PCBS" at 12054.46,2093.64 h60
  text "TO MEET OR EXCEED THE REQUIREMENTS OF:" at 12054.46,1995.64 h60
  text "X" at 11680.96,1859.13 h60
  text "ANSI IPC-A-600F CLASS ->" at 11819.96,1859.13 h60
  text "X" at 13459.02,1859.13 h60
  text "2" at 13577.96,1859.14 h60
  text "1" at 13262.96,1857.64 h60
  text "3" at 13931.96,1857.64 h60
  text "X" at 12495.02,1699.64 h60
  text "RoHS" at 12631.96,1699.64 h60
  text "OTHER" at 13276.36,1699.64 h60
  text "PER ORDER" at 13673.42,1699.64 h60
  text "ALL BOARDS MUST MEET OR EXCEED UL94-V0 REQUIREMENTS." at 11357,1534 h60
  text "PCB MUST BEAR THE UL94V-0 UL REGISTERED MATERIAL ID NUMBER" at 11357,1414 h60
  text "ADDITIONAL REQUIREMENTS:" at 11329.46,1240.64 h60
  text "MICROSECTION:" at 11404.23,1125.64 h60
  text "YES" at 12309.96,1125.64 h60
  text "REQUIRED" at 13171.46,969.49 h60
  text "BARE BOARD ELEC. TEST:" at 11404.23,966.64 h60
  text "NONE" at 12709.96,966.64 h60
  text "X" at 13044.46,966.64 h60
  text "PER ORDER" at 13763.46,966.64 h60
  text ".Layer_Name" at 577,-858.49 h60
M11 Gerber Information:
  lines w10: -292,-930.17 6308,-930.17 ; -292,-726.83 6310,-726.83 ; -292,-523.5 -292,-1133.5 3713,-1133.5 6310,-1133.5 6310,-523.5 -291.5,-523.5 -291.5,-1133.5 1284,-1133.5 ; 2173,-1133.5 2173,-523.5 ; 3440,-726.83 3440,-523.5 ; 4280,-726.83 4280,-523.5 ; 4902,-1140 4902,-937.17
  text "ALL ARTWORK VIEWED FROM TOP SIDE" at -228.5,-655.67 h60
  text "BOARD #:" at 2248,-655.67 h60
  text ".PRJ_Number" at 2793.5,-655.67 h60
  text "REV:" at 3638,-655.67 h60
  text ".PCB_Rev" at 3929.5,-655.67 h60
  text "SVN REV:" at 4476,-655.67 h60
  text ".VersionControl_RevNumber" at 4982,-655.67 h60
  text "LAYER NAME =" at -228.5,-858.49 h60
  text "TID #:" at 2248,-859 h60
  text ".TID" at 2793.5,-859 h60
  text "PLOT NAME =" at -228.5,-1064.34 h60
  text ".plot_File_Name" at 577,-1064.34 h60
  text "GENERATED    :" at 2250,-1064.34 h60
  text ".Print_Date" at 3119.5,-1064.34 h60
  text ".Print_Time" at 3848.5,-1064.34 h60
  text "TEXAS INSTRUMENTS" at 5113,-1064.34 h60
M12 Stackup:
  drawing of 295 lines, arcs and shapes, not listed
  text "Layer" at 9750.58,7770 h60
  text "Name" at 10160.49,7770 h60
  text "Material" at 11090.23,7770 h60
  text "Thickness" at 11950,7770 h60
  text "Constant" at 12599.84,7770 h60
  text "Board Layer Stack" at 13169.7,7770 h60
  text "1" at 9750.58,7650 h60
  text "Top Overlay" at 10160.49,7650 h60
  text "2" at 9750.58,7530 h60
  text "Top Solder" at 10160.49,7530 h60
  text "Solder Resist" at 11090.23,7530 h60
  text "0.40mil" at 11950,7530 h60
  text "3.5" at 12599.84,7530 h60
  text "3" at 9750.58,7410 h60
  text "Top Layer" at 10160.49,7410 h60
  text "Copper" at 11090.23,7410 h60
  text "2.80mil" at 11950,7410 h60
  text "4" at 9750.58,7290 h60
  text "Dielectric1" at 10160.49,7290 h60
  text "FR-4" at 11090.23,7290 h60
  text "14.20mil" at 11950,7290 h60
  text "4.8" at 12599.84,7290 h60
  text "5" at 9750.58,7170 h60
  text "MidLayer1" at 10160.49,7170 h60
  text "Copper" at 11090.23,7170 h60
  text "2.80mil" at 11950,7170 h60
  text "6" at 9750.58,7050 h60
  text "Dielectric2" at 10160.49,7050 h60
  text "FR-4" at 11090.23,7050 h60
  text "21.60mil" at 11950,7050 h60
  text "4.8" at 12599.84,7050 h60
  text "7" at 9750.58,6930 h60
  text "MidLayer2" at 10160.49,6930 h60
  text "Copper" at 11090.23,6930 h60
  text "2.80mil" at 11950,6930 h60
  text "8" at 9750.58,6810 h60
  text "Dielectric3" at 10160.49,6810 h60
  text "FR-4" at 11090.23,6810 h60
  text "14.20mil" at 11950,6810 h60
  text "4.8" at 12599.84,6810 h60
  text "9" at 9750.58,6690 h60
  text "Bottom Layer" at 10160.49,6690 h60
  text "Copper" at 11090.23,6690 h60
  text "2.80mil" at 11950,6690 h60
  text "10" at 9750.58,6570 h60
  text "Bottom Solder" at 10160.49,6570 h60
  text "Solder Resist" at 11090.23,6570 h60
  text "0.40mil" at 11950,6570 h60
  text "3.5" at 12599.84,6570 h60
  text "11" at 9750.58,6450 h60
  text "Bottom Overlay" at 10160.49,6450 h60
  text ".Layer_Name" at 577,-858.49 h60
M13 Component Bodies Top:
  text ".Layer_Name" at 577,-858.49 h60
M14 Component Bodies Bottom:
  text ".Layer_Name" at 577,-858.49 h60
M15 Courtyards Top:
  text ".Layer_Name" at 577,-858.49 h60
M16 Courtyards Bottom:
  text ".Layer_Name" at 577,-858.49 h60
Drill Drawing:
  circle w10: c6693.72,887.64 r27.63
  circle w10: c6693.72,763.32 r16.58
  circle w10: c6693.72,763.32 r27.63
  lines w10: 6666.09,-120.73 6679.9,-120.73 6679.9,-134.54 6707.53,-134.54 6707.53,-120.73 6721.34,-120.73 6721.34,-93.1 6707.53,-93.1 6707.53,-79.29 6679.9,-79.29 6679.9,-93.1 6666.09,-93.1 6666.09,-120.73 ; 6666.09,-10.22 6693.72,3.59 6721.34,-10.22 6707.53,17.4 6721.34,45.03 6693.72,31.22 6666.09,45.03 6679.9,17.4 6666.09,-10.22 ; 6666.09,127.91 6679.9,127.91 6693.72,114.1 6707.53,127.91 6721.34,127.91 6707.53,141.72 6721.34,155.54 6707.53,155.54 6693.72,169.35 6679.9,155.54 6666.09,155.54 6679.9,141.72 6666.09,127.91 ; 6666.09,238.42 6693.72,252.23 6721.34,238.42 6707.53,266.04 6721.34,293.67 6693.72,279.86 6666.09,293.67 6679.9,266.04 6666.09,238.42 ; 6666.09,417.99 6721.34,417.99 6693.72,362.74 6666.09,417.99 ; 6666.09,542.31 6721.34,542.31 6693.72,487.06 6666.09,542.31 ; 6666.09,611.38 6721.34,611.38 6721.34,666.63 6666.09,666.63 6666.09,611.38 ; 6666.09,998.15 6679.9,998.15 6693.72,984.34 6707.53,998.15 6721.34,998.15 6707.53,1011.96 6721.34,1025.78 6707.53,1025.78 6693.72,1039.59 6679.9,1025.78 6666.09,1025.78 6679.9,1011.96 6666.09,998.15 ; 6666.09,1136.28 6693.72,1108.66 6721.34,1136.28 6693.72,1163.91 6666.09,1136.28 ; 6677.14,249.47 6693.72,257.75 6710.29,249.47 6702.01,266.04 6710.29,282.62 6693.72,274.33 6677.14,282.62 6685.43,266.04 6677.14,249.47 ; 6677.14,406.94 6710.29,406.94 6693.72,373.79 6677.14,406.94 ; 6677.14,622.43 6710.29,622.43 6710.29,655.58 6677.14,655.58 6677.14,622.43 ; 6677.14,1003.67 6685.43,1003.67 6693.72,995.39 6702.01,1003.67 6710.29,1003.67 6702.01,1011.96 6710.29,1020.25 6702.01,1020.25 6693.72,1028.54 6685.43,1020.25 6677.14,1020.25 6685.43,1011.96 6677.14,1003.67
  lines w12: 6616,-171.84 9847.49,-171.84 ; 6616,1195.68 9847.49,1195.68 ; 6953.86,-296.16 6953.86,1320 ; 7285.86,-296.16 7285.86,1320 ; 7922.43,-296.16 7922.43,1320 ; 8181.57,-296.16 8181.57,1320 ; 8556.72,-296.16 8556.72,1320 ; 9281.05,-296.16 9281.05,1320 ; 6616,-296.16 9847.49,-296.16 9847.49,1320 6616,1320 6616,-296.16
  text "Symbol" at 6690.59,1232.98 h72
  text "Quantity" at 6991.16,1232.98 h72
  text "Finished Hole Size" at 7323.16,1232.98 h72
  text "Plated" at 7959.72,1232.98 h72
  text "Hole Type" at 8218.86,1232.98 h72
  text "Drill Layer Pair" at 8594.02,1232.98 h72
  text "Hole Tolerance" at 9318.35,1232.98 h72
  text "8" at 6991.16,1108.66 h60
  text "7.87mil (0.200mm)" at 7323.16,1108.66 h60
  text "PTH" at 7959.72,1108.66 h60
  text "Round" at 8218.86,1108.66 h60
  text "Top Layer - Bottom Layer" at 8594.02,1108.66 h60
  text "4" at 6991.16,984.34 h60
  text "8.00mil (0.203mm)" at 7323.16,984.34 h60
  text "PTH" at 7959.72,984.34 h60
  text "Round" at 8218.86,984.34 h60
  text "Top Layer - Bottom Layer" at 8594.02,984.34 h60
  text "128" at 6991.16,860.02 h60
  text "10.00mil (0.254mm)" at 7323.16,860.02 h60
  text "PTH" at 7959.72,860.02 h60
  text "Round" at 8218.86,860.02 h60
  text "Top Layer - Bottom Layer" at 8594.02,860.02 h60
  text "23" at 6991.16,735.7 h60
  text "20.00mil (0.508mm)" at 7323.16,735.7 h60
  text "PTH" at 7959.72,735.7 h60
  text "Round" at 8218.86,735.7 h60
  text "Top Layer - Bottom Layer" at 8594.02,735.7 h60
  text "77" at 6991.16,611.38 h60
  text "28.00mil (0.711mm)" at 7323.16,611.38 h60
  text "PTH" at 7959.72,611.38 h60
  text "Round" at 8218.86,611.38 h60
  text "Top Layer - Bottom Layer" at 8594.02,611.38 h60
  text "3" at 6991.16,487.06 h60
  text "31.00mil (0.787mm)" at 7323.16,487.06 h60
  text "PTH" at 7959.72,487.06 h60
  text "Round" at 8218.86,487.06 h60
  text "Top Layer - Bottom Layer" at 8594.02,487.06 h60
  text "16" at 6991.16,362.74 h60
  text "35.04mil (0.890mm)" at 7323.16,362.74 h60
  text "PTH" at 7959.72,362.74 h60
  text "Round" at 8218.86,362.74 h60
  text "Top Layer - Bottom Layer" at 8594.02,362.74 h60
  text "2" at 6991.16,238.42 h60
  text "43.31mil (1.100mm)" at 7323.16,238.42 h60
  text "PTH" at 7959.72,238.42 h60
  text "Round" at 8218.86,238.42 h60
  text "Top Layer - Bottom Layer" at 8594.02,238.42 h60
  text "2" at 6991.16,114.1 h60
  text "50.00mil (1.270mm)" at 7323.16,114.1 h60
  text "PTH" at 7959.72,114.1 h60
  text "Round" at 8218.86,114.1 h60
  text "Top Layer - Bottom Layer" at 8594.02,114.1 h60
  text "4" at 6991.16,-10.22 h60
  text "61.81mil (1.570mm)" at 7323.16,-10.22 h60
  text "PTH" at 7959.72,-10.22 h60
  text "Round" at 8218.86,-10.22 h60
  text "Top Layer - Bottom Layer" at 8594.02,-10.22 h60
  text "4" at 6991.16,-134.54 h60
  text "128.00mil (3.251mm)" at 7323.16,-134.54 h60
  text "PTH" at 7959.72,-134.54 h60
  text "Round" at 8218.86,-134.54 h60
  text "Top Layer - Bottom Layer" at 8594.02,-134.54 h60
  text "271 Total" at 6991.16,-258.86 h60
  text ".Layer_Name" at 577,-858.49 h60
M17 Embedded Cavity:
  text ".Layer_Name" at 577,-858.49 h60
M18 Embedded Assembly:
  text ".Layer_Name" at 577,-858.49 h60
M19 Embedded Keepout:
  text ".Layer_Name" at 577,-858.49 h60

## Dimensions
0,0 to 5700,0 on M2 Board Dimensions
0,0 to 0,3550 on M2 Board Dimensions
0,-400 to 1000,-400 on M2 Board Dimensions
